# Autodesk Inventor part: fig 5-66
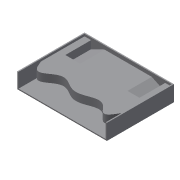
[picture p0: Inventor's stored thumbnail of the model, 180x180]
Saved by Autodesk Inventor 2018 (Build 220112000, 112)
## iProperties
Created: 2004-05
Part Number: fig 5-66
Document SubType Name: Modeling
Designer: CADCIM Technologies
Manufacturer: Standard
Standards Organization: Custom
Density: 1 g/cm^3
Material: Generic
Appearance: Default
Author: CADCIM Technologies
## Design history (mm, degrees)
sketch "Sketch1"
  geometry: L1 (-40, -30)-(40, -30); L2 (40, -30)-(40, 30); L3 (40, 30)-(-40, 30); L4 (-40, 30)-(-40, -30); 1 further point
  constraints: 8 end point, 2 parallel, 1 horizontal, 1 perpendicular, 1 other
  dimensions: "d0" = 80 distance of L1.start L1.end; "d1" = 60 distance of L3.end L1.start; "d2" = 30 distance from line of point (0, 0) L1; "d3" = 40 distance from line of point (0, 0) L4
extrude "Extrusion1" new body sketch "Sketch1" distance "d4" = 14; taper "d5" = 0 deg
shell "Shell1" dims "d6" = 1
workplane "Work Plane1"
sketch "Sketch2"
  geometry: L1 (78, -13)-(78, -11.813); L2 (0, -11.813)-(0, -13); L3 (0, -13)-(78, -13); L4 (0, -11.813)-(17.826, -3.295); L5 (17.826, -3.295)-(60.174, -3.295); L6 (60.174, -3.295)-(78, -11.813); L7 (79, -13.795)-(78, -13.795); L8 (78, 0)-(78, -13) reference; L9 (0, -13)-(0, 0) reference; L10 (78, -13)-(0, -13) reference
  constraints: 14 end point, 3 collinear, 2 equal length, 2 vertical, 1 horizontal alignment, 1 parallel, 1 point on line
extrude "Extrusion2" join sketch "Sketch2" stored distance "d8" = 14; taper "d9" = 0 deg
workplane "Work Plane2"
sketch "Sketch3"
  geometry: 7 further points
  constraints: 7 other
extrude "Extrusion7" join sketch "Sketch3" distance "d27" = 7; taper "d28" = 0 deg
body "Solid1"
other parameters: "d7" = 23, "d18" = 4, "d29" = 7
